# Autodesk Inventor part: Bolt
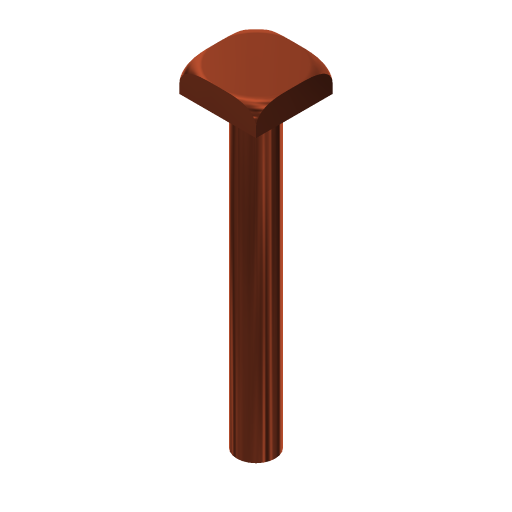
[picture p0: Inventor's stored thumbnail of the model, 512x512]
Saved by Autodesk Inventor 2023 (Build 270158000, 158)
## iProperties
Created: 2009-04
Part Number: Bolt
Document SubType Name: Modeling
Designer: Sham
Density: 8.92 g/cm^3
Material: Copper, Alloy
Appearance: Copper - Satin
Author: Sham
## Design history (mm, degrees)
sketch "Sketch1"
  geometry: L1 (-12, 12)-(12, 12); L2 (12, 12)-(12, -12); L3 (12, -12)-(-12, -12); L4 (-12, -12)-(-12, 12); 1 further point
  constraints: 8 end point, 2 parallel, 2 perpendicular, 1 horizontal, 1 other
  dimensions: "d0" = 24 distance of L1.start L1.end; "d1" = 12 distance from line of L2 point (0, 0); "d2" = 12 distance from line of L1 point (0, 0)
extrude "Extrusion1" new body sketch "Sketch1" distance "d3" = 8; taper "d4" = 0 deg
sketch "Sketch2"
  geometry: C1 r 6 at (0, 0)
  constraints: 1 centre point
  dimensions: "d5" = 12 diameter of C1
extrude "Extrusion2" join sketch "Sketch2" distance "d6" = 96; taper "d7" = 0 deg
workpoint "Work Point1"
workplane "Work Plane1"
sketch "Sketch3"
  geometry: L1 (33.941, 5)-(33.941, 6); L2 (28.941, 0)-(28.405, 0); L3 (16.971, 125.007)-(16.971, -22.043) reference; A1 r 5 centre (28.941, 5) between (28.941, 0) and (33.941, 5); 1 further point
  constraints: 4 end point, 2 point on circle, 2 point on line, 2 tangent, 1 centre point, 1 perpendicular
  dimensions: "d10" = 5 radius of A1
revolve "Revolution1" sketch "Sketch3" stored, may be unused: angle "d12" = 90 deg
body "Solid1"
other parameters: "d11" = 90 deg
